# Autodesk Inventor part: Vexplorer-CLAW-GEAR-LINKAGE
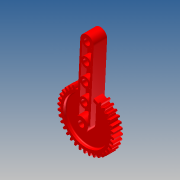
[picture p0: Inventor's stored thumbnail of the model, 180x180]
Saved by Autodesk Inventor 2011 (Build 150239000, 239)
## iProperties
Created: 2007-10
Part Number: Vexplorer-CLAW-GEAR-LINKAGE
Document SubType Name: Modeling
Material: ABS Plastic
Density: 1.06 g/cm^3
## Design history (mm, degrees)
feature "Base1"
workplane "Work Plane1"
body "Solid1"
